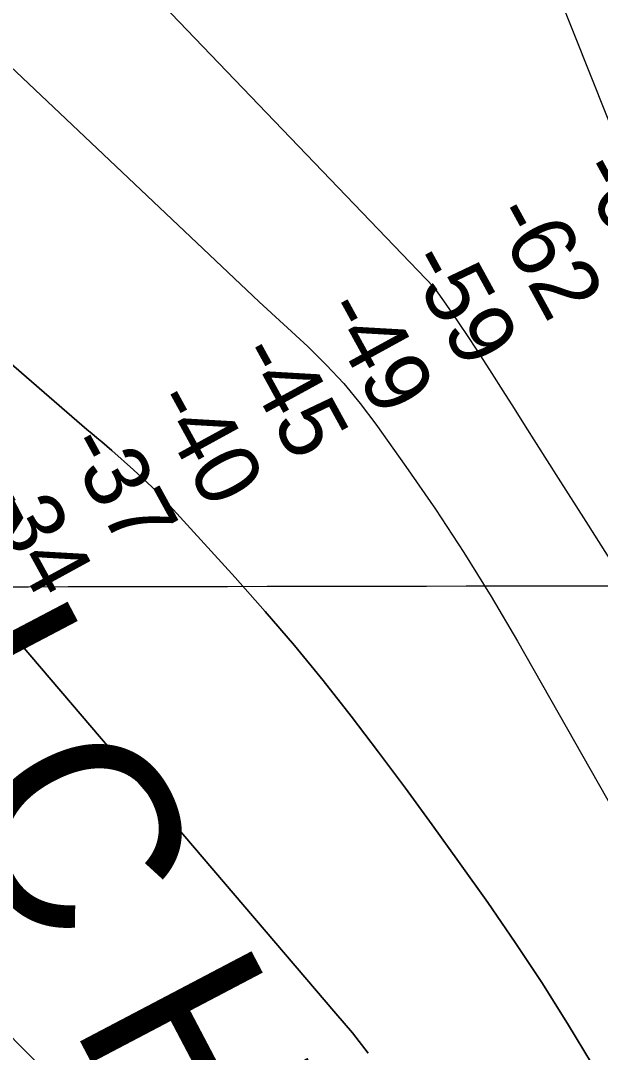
# Model space of a CAD drawing. Extents: x 3329297 to 3367176, y 649250 to 674653.
# Drawn here: x 3340552 to 3341150, y 666285 to 667351 of the extents above; entities that cross this region are included whole.
import ezdxf

# ---------------------------------------------------------------- set-up
doc = ezdxf.new("R2010")
doc.units = 0
for name, color, linetype in [('V-CHAN-NAID', 7, 'Continuous'), ('V-GRID-MAJR', 7, 'Continuous'), ('V-RIVR-EDGE', 7, 'Continuous'), ('V-RIVR-IDEN', 7, 'Continuous'), ('V-RIVR-RANG', 7, 'Continuous'), ('V-TOPO-DPTH', 7, 'Continuous'), ('V-TOPO-MAJR', 7, 'Continuous'), ('V-TOPO-MINR', 7, 'Continuous')]:
    doc.layers.add(name, color=color, linetype=linetype)

msp = doc.modelspace()

# ---------------------------------------------------------------- linework, layer by layer
at = {"layer": 'V-GRID-MAJR'}
msp.add_spline([(3333412.313, 666754.8420000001), (3338670.2060000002, 666762.872), (3343928.099, 666771.667), (3349185.99, 666781.226), (3354443.88, 666791.55), (3359701.768, 666802.639), (3364959.654, 666814.493), (3364959.6550000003, 666814.493)], degree=3, dxfattribs=at)
at = {"layer": 'V-RIVR-EDGE'}
msp.add_spline([(3342816.412489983, 664076.7034879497), (3342812.7598693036, 664100.7302350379), (3342811.243187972, 664114.6948926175), (3342810.4934775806, 664125.1674268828), (3342811.66742752, 664129.4303568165), (3342815.9380288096, 664131.3588117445), (3342822.141879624, 664130.9556684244), (3342827.577800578, 664133.6568478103), (3342827.978067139, 664138.6972967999), (3342825.7126343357, 664163.5222892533), (3342823.0124138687, 664169.3460108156), (3342818.010321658, 664185.2583017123), (3342816.4955581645, 664199.9985605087), (3342816.9054139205, 664208.9170155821), (3342818.0985422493, 664220.9359576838), (3342817.3382837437, 664227.1426852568), (3342814.6639541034, 664243.4370232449), (3342809.2692666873, 664257.4112700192), (3342808.5099671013, 664264.0057982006), (3342808.918863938, 664272.5364526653), (3342814.794367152, 664296.1779059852), (3342814.817381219, 664305.4851205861), (3342810.586095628, 664319.456490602), (3342799.7756245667, 664338.8733707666), (3342790.8840192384, 664350.1416435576), (3342779.6627335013, 664360.2522680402), (3342778.5117976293, 664365.2965527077), (3342779.2969880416, 664369.1726409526), (3342779.6886243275, 664370.7228844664), (3342785.908776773, 664376.9123514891), (3342798.3462049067, 664388.1278837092), (3342804.183351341, 664396.2573126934), (3342807.7080779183, 664410.2095043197), (3342807.3365789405, 664416.8030735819), (3342805.021282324, 664421.4624343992), (3342805.0279947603, 664424.177038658), (3342805.054844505, 664435.0354556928), (3342805.482919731, 664451.3221223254), (3342803.586109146, 664468.3901436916), (3342800.1380961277, 664485.4620007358), (3342800.1543977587, 664492.0546110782), (3342800.5517875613, 664495.9316582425), (3342805.601825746, 664499.409397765), (3342810.274611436, 664507.153902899), (3342811.4543148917, 664513.7436364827), (3342812.6493610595, 664526.5381798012), (3342808.839438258, 664554.0816121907), (3342808.4775284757, 664564.5531875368), (3342811.984994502, 664571.5249682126), (3342819.756349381, 664577.7105995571), (3342825.2124076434, 664588.5555917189), (3342825.6203455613, 664596.6984455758), (3342825.2507644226, 664604.0676160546), (3342821.38905997, 664610.6698155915), (3342817.543657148, 664623.8646254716), (3342808.6443804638, 664632.0304933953), (3342807.4982391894, 664639.0137811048), (3342807.5145408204, 664645.6063914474), (3342805.5889626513, 664651.0403945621), (3342795.54738037, 664667.7407526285), (3342786.278522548, 664683.2757910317), (3342782.785440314, 664682.1210194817), (3342779.3038651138, 664685.6198552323), (3342772.3560574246, 664698.8223364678), (3342765.0051064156, 664705.8209668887), (3342757.6599089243, 664715.1464009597), (3342754.9596884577, 664720.9701225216), (3342754.970236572, 664725.235929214), (3342756.919787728, 664729.496941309), (3342762.3624211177, 664734.912724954), (3342763.164872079, 664745.7692241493), (3342759.3434422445, 664768.6590492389), (3342756.6585644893, 664780.687580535), (3342750.4921115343, 664796.214947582), (3342738.9127516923, 664818.348349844), (3342728.8817175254, 664839.3145146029), (3342718.826710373, 664850.5856641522), (3342704.5269927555, 664870.3989752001), (3342673.2052819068, 664906.9299048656), (3342667.0254040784, 664917.0280633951), (3342662.4005643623, 664928.6735886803), (3342645.7730841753, 664948.1048526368), (3342638.8156872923, 664957.4293277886), (3342632.6415629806, 664969.8542899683), (3342630.7226972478, 664978.0028973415), (3342626.8619517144, 664984.9928974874), (3342614.8689004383, 664996.6566422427), (3342611.3854073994, 664999.3798767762), (3342609.8389995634, 665001.3227154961), (3342609.8514655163, 665006.3641234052), (3342606.758649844, 665010.2498008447), (3342597.8641677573, 665020.3546718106), (3342593.2230264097, 665025.4075867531), (3342592.4666035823, 665033.1655167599), (3342590.9432098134, 665044.415570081), (3342589.416939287, 665054.5022215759), (3342588.2803872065, 665065.3635153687), (3342585.9823511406, 665077.0032871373), (3342585.2307229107, 665086.7002201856), (3342585.254695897, 665096.3952353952), (3342584.878402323, 665101.0498016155), (3342582.947070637, 665104.1570010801), (3342580.2458912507, 665109.5929220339), (3342577.1617058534, 665116.9688049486), (3342577.1760896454, 665122.7858140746), (3342577.1981447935, 665131.7052280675), (3342577.2249945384, 665142.5636451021), (3342577.2537621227, 665154.1976633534), (3342576.123922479, 665167.7735614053), (3342572.696046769, 665192.9892312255), (3342566.9336960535, 665215.1082496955), (3342563.4789705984, 665229.465502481), (3342558.8512541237, 665239.947625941), (3342557.310599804, 665244.2172683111), (3342555.3994054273, 665255.4682805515), (3342553.1052050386, 665268.6592547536), (3342549.2665146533, 665284.5686688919), (3342541.5661198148, 665307.0802825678), (3342537.3367520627, 665321.8272538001), (3342531.9526127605, 665340.067307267), (3342533.512445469, 665343.5536770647), (3342533.5277881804, 665349.7584867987), (3342526.981205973, 665368.3892176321), (3342525.457812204, 665379.6392709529), (3342523.5399053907, 665388.1756789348), (3342518.149053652, 665403.7011281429), (3342515.4651348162, 665416.1174600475), (3342514.3381719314, 665430.8567599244), (3342508.5700676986, 665450.6489747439), (3342503.190722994, 665470.8280312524), (3342492.3812108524, 665490.6327120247), (3342491.626705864, 665499.166243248), (3342490.8741187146, 665508.475375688), (3342486.2809233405, 665532.9183210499), (3342483.597004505, 665545.3346529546), (3342477.8106808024, 665557.7586562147), (3342475.9272950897, 665580.2558860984), (3342474.7984143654, 665594.2195847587), (3342470.1726157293, 665605.4773094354), (3342467.8678672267, 665614.4024769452), (3342467.1296638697, 665629.5286185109), (3342466.3885837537, 665643.491358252), (3342466.8224124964, 665662.1048285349), (3342467.2533644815, 665679.5548969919), (3342463.4146740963, 665695.4643111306), (3342454.928129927, 665713.7120359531), (3342445.6669434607, 665732.3494792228), (3342448.389219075, 665735.4451716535), (3342449.5516619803, 665735.0544942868), (3342454.5777271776, 665728.8372185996), (3342456.1327652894, 665730.3845853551), (3342456.133724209, 665730.7723859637), (3342455.367712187, 665734.6523098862), (3342442.2227661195, 665750.9725387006), (3342428.700567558, 665771.5595331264), (3342413.6482627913, 665800.6819766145), (3342398.602670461, 665832.5190243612), (3342380.4671392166, 665869.4051513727), (3342358.860580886, 665914.0559208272), (3342350.0015788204, 665938.5094143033), (3342337.2655295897, 665963.3602975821), (3342312.2023279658, 666021.5927186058), (3342297.1692015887, 666058.4711742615), (3342281.741562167, 666092.6359845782), (3342274.8100561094, 666112.4310761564), (3342267.5003386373, 666136.1051327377), (3342262.9205681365, 666165.9772866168), (3342261.430736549, 666190.8003612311), (3342261.4499149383, 666198.556373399), (3342257.5699910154, 666197.7903613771), (3342255.2479819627, 666199.7351179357), (3342252.934603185, 666205.1700799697), (3342252.565022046, 666212.5392504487), (3342252.5813236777, 666219.1318607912), (3342250.2880822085, 666232.7106356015), (3342241.8197575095, 666258.3265719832), (3342236.0708316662, 666285.8747989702), (3342231.8126963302, 666288.9877519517), (3342227.553602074, 666291.7129043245), (3342219.0488384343, 666302.5924175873), (3342218.6715859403, 666306.8591831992), (3342219.0728114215, 666312.2874327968), (3342210.1581920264, 666314.2484909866), (3342205.12829115, 666318.9145642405), (3342203.978314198, 666324.3466495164), (3342203.99269799, 666330.1636586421), (3342202.075750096, 666339.0878672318), (3342191.6482850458, 666356.5647854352), (3342180.044952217, 666369.0031724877), (3342175.412441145, 666377.5462929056), (3342164.9897706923, 666396.9622141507), (3342154.5805251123, 666421.8073439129), (3342139.946706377, 666463.3384479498), (3342130.699903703, 666487.7929003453), (3342122.98991967, 666506.4265079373), (3342111.795483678, 666527.3955494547), (3342098.676428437, 666554.1863946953), (3342094.827189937, 666565.8300021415), (3342092.5397019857, 666581.7355806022), (3342088.6933402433, 666594.5425898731), (3342085.2482039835, 666612.7778487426), (3342082.168813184, 666622.0927346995), (3342072.8855715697, 666631.8107639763), (3342063.224118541, 666645.4077582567), (3342057.437794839, 666657.8317615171), (3342049.7316464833, 666678.0165715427), (3342048.217841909, 666693.1446309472), (3342050.165475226, 666696.6300418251), (3342050.960254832, 666704.3841361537), (3342046.7059551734, 666709.0482915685), (3342039.356922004, 666716.8225232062), (3342032.407196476, 666729.2494032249), (3342015.8104017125, 666761.0902866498), (3342003.061886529, 666780.8997620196), (3341996.0949004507, 666786.3462310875), (3341994.9468413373, 666792.5539175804), (3341992.629626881, 666796.4376771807), (3341982.9729684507, 666811.9736745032), (3341967.1306786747, 666835.2810267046), (3341953.5912195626, 666848.8876101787), (3341946.6319048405, 666857.4364841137), (3341940.452985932, 666867.9224432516), (3341935.814721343, 666874.1387600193), (3341919.1642270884, 666884.2628093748), (3341915.6884054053, 666890.0884487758), (3341911.4475306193, 666900.1818127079), (3341899.847074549, 666913.7836015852), (3341894.8238861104, 666921.1642790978), (3341889.03276781, 666931.6492793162), (3341869.317266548, 666956.9052237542), (3341855.0127543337, 666974.7795317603), (3341848.8175337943, 666978.6728805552), (3341839.5304565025, 666986.8397073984), (3341829.093402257, 667000.4386195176), (3341821.7616296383, 667015.1932621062), (3341819.0709983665, 667024.8949897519), (3341817.1473380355, 667031.1045940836), (3341806.3080993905, 667038.8874559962), (3341788.125581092, 667056.7713531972), (3341778.463169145, 667069.9805468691), (3341769.5590978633, 667076.207411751), (3341762.975117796, 667079.7139188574), (3341756.0177209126, 667089.0383940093), (3341748.28759957, 667099.5281888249), (3341738.624228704, 667112.3495818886), (3341730.887394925, 667120.1247724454), (3341719.2869388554, 667133.7265613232), (3341714.656345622, 667143.0452829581), (3341706.5460950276, 667156.6384415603), (3341694.949474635, 667171.7914328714), (3341682.2191789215, 667198.9691198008), (3341673.732634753, 667217.2168446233), (3341665.656905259, 667244.7708251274), (3341658.3529413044, 667270.7716853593), (3341654.4998671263, 667280.8640903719), (3341646.7850884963, 667297.5586949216), (3341633.668910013, 667325.5129419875), (3341621.3129900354, 667347.2604614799), (3341603.9194978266, 667370.5716493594), (3341601.613790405, 667379.1090162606), (3341595.053783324, 667392.3105385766), (3341586.5720337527, 667412.4972664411), (3341578.097955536, 667435.7863991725), (3341568.43362575, 667448.219991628), (3341554.132949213, 667467.6455020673), (3341537.518893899, 667492.5059745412), (3341516.655333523, 667523.9696054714), (3341476.0791486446, 667581.8525826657), (3341429.711845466, 667650.2205600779), (3341398.0282248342, 667697.2230650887), (3341370.980950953, 667737.2336521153), (3341354.758531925, 667763.644368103), (3341343.5487532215, 667778.4085998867), (3341338.9047351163, 667782.298113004), (3341332.3313031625, 667790.0704268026), (3341325.39020791, 667805.9875122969), (3341317.6543330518, 667814.1505034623), (3341305.2773168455, 667827.3664095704), (3341300.6380933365, 667833.19492573), (3341282.889403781, 667869.6922932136), (3341259.7239716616, 667911.244493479), (3341224.57795422, 667969.5018464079), (3341190.5723245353, 668018.4491079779), (3341159.668140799, 668067.0008975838), (3341126.024420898, 668105.476583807), (3341085.807269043, 668151.7245838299), (3341034.769098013, 668213.1236573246), (3340998.796656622, 668250.8294958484), (3340967.0746792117, 668282.3199765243), (3340929.9206165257, 668312.6604802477), (3340887.354605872, 668349.9948197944), (3340852.52159332, 668378.0027663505), (3340818.0763813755, 668406.0097539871), (3340783.6436353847, 668439.0581495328), (3340747.6692761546, 668475.9883868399), (3340722.9200383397, 668504.3592020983), (3340704.3583497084, 668525.734263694), (3340693.9155419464, 668537.0063721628), (3340680.745663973, 668543.2437851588), (3340672.610481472, 668546.7541279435), (3340664.4810524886, 668552.5912743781), (3340650.9348809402, 668563.4832535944), (3340645.9068979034, 668568.9249280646), (3340640.884668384, 668576.6934061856), (3340634.69807812, 668584.0769604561), (3340619.617005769, 668601.5653856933), (3340609.5418613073, 668604.6927224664), (3340603.7354002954, 668608.9729129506), (3340599.0952178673, 668614.4136285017), (3340595.621314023, 668621.0148691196), (3340589.431847, 668627.2350215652), (3340567.761041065, 668645.9031502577), (3340549.9548163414, 668659.1324812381), (3340496.933531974, 668702.6975213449), (3340430.762506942, 668760.6437872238), (3340383.932607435, 668798.7642761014), (3340346.7670377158, 668824.451172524), (3340316.957213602, 668845.0784415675), (3340289.8562402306, 668863.3721945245), (3340255.4119872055, 668891.7669827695), (3340209.373031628, 668936.0903635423), (3340181.1297526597, 668962.9186066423), (3340159.060598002, 668977.3218875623), (3340134.28834612, 668996.3854882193), (3340120.7469691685, 669009.2164704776), (3340113.399853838, 669017.7663033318), (3340109.9240321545, 669023.591942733), (3340107.6029820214, 669025.9244998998), (3340099.8488876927, 669026.7192795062), (3340094.4225559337, 669027.896106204), (3340089.386901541, 669030.2353758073), (3340085.13643756, 669036.4507336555), (3340084.7649385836, 669043.0443029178), (3340082.0580056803, 669046.1534202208), (3340066.189825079, 669058.990155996), (3340051.0962867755, 669071.4371733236), (3340041.8044148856, 669077.6649971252), (3339987.6072627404, 669116.1915060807), (3339929.5186796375, 669149.2983957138), (3339882.276047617, 669177.337027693), (3339823.8034995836, 669211.9960786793), (3339768.8192391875, 669245.8708981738), (3339704.9395377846, 669289.4627880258), (3339659.643580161, 669320.5990302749), (3339613.9790003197, 669359.4922436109), (3339576.0320758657, 669382.8542542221), (3339562.8717870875, 669392.9696733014), (3339559.38541729, 669394.5295060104), (3339555.894252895, 669394.1503356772), (3339553.169100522, 669389.8912414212), (3339550.8394201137, 669388.7335931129), (3339546.194443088, 669392.2353056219), (3339540.385105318, 669395.3520942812), (3339537.276946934, 669393.0329619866), (3339533.010181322, 669392.6557094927), (3339518.6749836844, 669398.12039803), (3339507.8328682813, 669404.7398581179), (3339498.9297559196, 669411.3545236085), (3339490.0103419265, 669411.3765787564), (3339486.5316434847, 669416.0388163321), (3339483.4330742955, 669417.5976901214), (3339473.3579298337, 669420.7250268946), (3339460.5777703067, 669427.7370821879), (3339447.7995286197, 669435.5247386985), (3339435.4090875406, 669443.3114362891), (3339423.800001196, 669453.423019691), (3339413.3571934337, 669464.6951281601), (3339407.9442865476, 669471.3011633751), (3339393.6158013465, 669479.4804561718), (3339378.1277499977, 669489.2138281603), (3339357.606921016, 669502.4498715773), (3339355.6736714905, 669504.7814698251), (3339358.392111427, 669506.3259598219), (3339359.5631846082, 669509.4254879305), (3339359.1792196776, 669510.977649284), (3339356.4751635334, 669515.2501684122), (3339347.17178461, 669516.8243849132), (3339341.3442273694, 669512.5729620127), (3339338.2437403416, 669513.3562345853), (3339320.8233983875, 669525.80900543), (3339311.1504383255, 669534.7523924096), (3339296.0607356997, 669548.7506121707), (3339293.349967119, 669550.3085270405), (3339286.3666794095, 669549.1623857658), (3339280.930758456, 669546.4612063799), (3339277.0527523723, 669546.4707955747), (3339268.141968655, 669549.9830561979), (3339250.7149142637, 669559.7212227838), (3339229.037395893, 669575.6747472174), (3339210.8385759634, 669586.9660340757), (3339202.3270998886, 669595.1309430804), (3339200.3986449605, 669599.4015443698), (3339200.024269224, 669604.8317118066), (3339198.1006088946, 669611.041316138), (3339183.005152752, 669622.712732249), (3339166.3536995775, 669632.4489809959)], degree=3, dxfattribs=at)
at = {"layer": 'V-TOPO-DPTH'}
for points in [[(3340515.784035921, 667018.4560572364), (3340604.4872390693, 666941.6365802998), (3340609.6230204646, 666937.2259392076), (3340614.7828812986, 666932.8438908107), (3340619.978861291, 666928.5047314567), (3340625.1989207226, 666924.1941647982), (3340630.4093139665, 666919.8725976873), (3340635.5827492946, 666915.5077819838), (3340640.7007477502, 666911.0780933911), (3340645.781788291, 666906.6051562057), (3340668.025848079, 666886.7730010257), (3340677.791540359, 666877.787262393), (3340687.3621001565, 666868.6044345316), (3340696.6399612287, 666859.125972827), (3340705.7226898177, 666849.4504218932), (3340773.1181377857, 666775.3602691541), (3340804.0907243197, 666740.4610839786), (3340834.4790536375, 666705.0725049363), (3340863.9909971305, 666668.949835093), (3340892.9186834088, 666632.3377713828), (3340921.1740805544, 666595.1858627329), (3340949.1182735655, 666557.8043177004), (3340976.595660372, 666520.0783180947), (3341003.761843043, 666482.1226821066), (3341033.830538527, 666439.5552035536), (3341062.1098839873, 666398.4595442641), (3341089.704056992, 666356.9207476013), (3341116.270471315, 666314.7172448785), (3341142.1517131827, 666272.0706047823)], [(3341142.1517131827, 666272.0706047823), (3341116.270471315, 666314.7172448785), (3341089.704056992, 666356.9207476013), (3341062.1098839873, 666398.4595442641), (3341033.830538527, 666439.5552035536), (3341003.761843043, 666482.1226821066), (3340976.595660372, 666520.0783180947), (3340949.1182735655, 666557.8043177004), (3340921.1740805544, 666595.1858627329), (3340892.9186834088, 666632.3377713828), (3340863.9909971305, 666668.949835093), (3340834.4790536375, 666705.0725049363), (3340804.0907243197, 666740.4610839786), (3340773.1181377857, 666775.3602691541), (3340705.7226898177, 666849.4504218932), (3340696.6399612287, 666859.125972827), (3340687.3621001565, 666868.6044345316), (3340677.791540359, 666877.787262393), (3340668.025848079, 666886.7730010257), (3340645.781788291, 666906.6051562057), (3340640.7007477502, 666911.0780933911), (3340635.5827492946, 666915.5077819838), (3340630.4093139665, 666919.8725976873), (3340625.1989207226, 666924.1941647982), (3340619.978861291, 666928.5047314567), (3340614.7828812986, 666932.8438908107), (3340609.6230204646, 666937.2259392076), (3340604.4872390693, 666941.6365802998), (3340515.784035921, 667018.4560572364)], [(3340771.2787898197, 666067.7999383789), (3340232.13029941, 666615.6760300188), (3340229.425696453, 666619.2219769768), (3340226.7191783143, 666622.7664623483), (3340222.617289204, 666628.1353334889), (3340219.2620926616, 666632.4489916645), (3340215.85793739, 666636.7229578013), (3340212.3803440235, 666640.9373858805), (3340208.853791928, 666645.112121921), (3340205.243418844, 666649.2132764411), (3340201.5703573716, 666653.2561164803), (3340197.803263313, 666657.2114847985), (3340193.9734808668, 666661.1085386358), (3340064.648950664, 666789.6459200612), (3340032.6700920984, 666821.2123163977), (3340000.5477135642, 666852.6309653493), (3339968.2100550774, 666883.8279932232), (3339935.7288766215, 666914.8772737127)], [(3340771.2787898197, 666067.7999383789), (3340232.13029941, 666615.6760300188), (3340229.425696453, 666619.2219769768), (3340226.7191783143, 666622.7664623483), (3340222.617289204, 666628.1353334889), (3340219.2620926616, 666632.4489916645), (3340215.85793739, 666636.7229578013), (3340212.3803440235, 666640.9373858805), (3340208.853791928, 666645.112121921), (3340205.243418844, 666649.2132764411), (3340201.5703573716, 666653.2561164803), (3340197.803263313, 666657.2114847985), (3340193.9734808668, 666661.1085386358), (3340064.648950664, 666789.6459200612), (3340032.6700920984, 666821.2123163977), (3340000.5477135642, 666852.6309653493), (3339968.2100550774, 666883.8279932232), (3339935.7288766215, 666914.8772737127)], [(3340508.91711353, 666756.4910139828), (3340876.943181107, 666324.9032894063), (3340894.2299979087, 666305.0608610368), (3340910.302791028, 666284.2228832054)], [(3340910.302791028, 666284.2228832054), (3340894.2299979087, 666305.0608610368), (3340876.943181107, 666324.9032894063), (3340508.91711353, 666756.4910139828)]]:
    msp.add_lwpolyline(points, dxfattribs=at)
at = {"layer": 'V-TOPO-MAJR'}
msp.add_lwpolyline([(3340406.3447181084, 667443.6637368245), (3340508.0460336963, 667334.2910983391), (3340797.918971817, 667060.3825286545), (3340848.01030639, 667014.0276851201), (3340867.0903643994, 666995.2371903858), (3340885.339846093, 666975.7171379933), (3340902.343463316, 666955.1027491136), (3340918.516504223, 666933.7588025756), (3340949.4640005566, 666890.1662050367), (3340979.8010785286, 666846.0399841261), (3341009.23178672, 666801.3364269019), (3341037.3029402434, 666755.7668652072), (3341064.4677239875, 666709.6199671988), (3341291.5625543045, 666310.19277351)], dxfattribs=at)
at = {"layer": 'V-TOPO-MINR'}
for points in [[(3339822.8375603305, 668309.1723428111), (3340137.134240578, 667960.7086974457), (3340184.451966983, 667908.5566591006), (3340231.97314176, 667856.5917744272), (3340279.799489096, 667804.9076202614), (3340327.829284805, 667753.4106197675), (3340378.9447437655, 667698.9277023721), (3340402.31641122, 667675.6972424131), (3340978.0768605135, 667075.4802250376), (3340990.534827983, 667057.9611672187), (3341002.7834024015, 667040.299616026), (3341014.7178872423, 667022.4243247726), (3341026.4429790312, 667004.4065401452), (3341037.999782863, 666986.2747368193), (3341049.5417473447, 666968.1335050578), (3341061.0614528, 666949.9781306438), (3341072.5663189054, 666931.8133277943), (3341106.5114003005, 666878.1453368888), (3341135.027142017, 666833.1710084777), (3341163.6088356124, 666788.2387345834)], [(3341173.8361770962, 667209.866692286), (3341056.328276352, 667505.072451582), (3341058.080097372, 667517.9068678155), (3341062.905037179, 667526.1118435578), (3341072.339655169, 667527.3726585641), (3341084.847391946, 667524.0040330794), (3341114.657445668, 667494.9964143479), (3341144.688970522, 667466.2226516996), (3341175.052702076, 667437.7996731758)], [(3340515.784035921, 667018.4560572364), (3340604.4872390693, 666941.6365802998), (3340609.6230204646, 666937.2259392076), (3340614.7828812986, 666932.8438908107), (3340619.978861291, 666928.5047314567), (3340625.1989207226, 666924.1941647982), (3340630.4093139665, 666919.8725976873), (3340635.5827492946, 666915.5077819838), (3340640.7007477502, 666911.0780933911), (3340645.781788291, 666906.6051562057), (3340668.025848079, 666886.7730010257), (3340677.791540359, 666877.787262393), (3340687.3621001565, 666868.6044345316), (3340696.6399612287, 666859.125972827), (3340705.7226898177, 666849.4504218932), (3340773.1181377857, 666775.3602691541), (3340804.0907243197, 666740.4610839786), (3340834.4790536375, 666705.0725049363), (3340863.9909971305, 666668.949835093), (3340892.9186834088, 666632.3377713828), (3340921.1740805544, 666595.1858627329), (3340949.1182735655, 666557.8043177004), (3340976.595660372, 666520.0783180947), (3341003.761843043, 666482.1226821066), (3341033.830538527, 666439.5552035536), (3341062.1098839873, 666398.4595442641), (3341089.704056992, 666356.9207476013), (3341116.270471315, 666314.7172448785), (3341142.1517131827, 666272.0706047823)], [(3339935.7288766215, 666914.8772737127), (3339968.2100550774, 666883.8279932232), (3340000.5477135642, 666852.6309653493), (3340032.6700920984, 666821.2123163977), (3340064.648950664, 666789.6459200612), (3340193.9734808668, 666661.1085386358), (3340197.803263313, 666657.2114847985), (3340201.5703573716, 666653.2561164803), (3340205.243418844, 666649.2132764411), (3340208.853791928, 666645.112121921), (3340212.3803440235, 666640.9373858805), (3340215.85793739, 666636.7229578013), (3340219.2620926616, 666632.4489916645), (3340222.617289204, 666628.1353334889), (3340226.7191783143, 666622.7664623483), (3340229.425696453, 666619.2219769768), (3340232.13029941, 666615.6760300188), (3340771.2787898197, 666067.7999383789)], [(3340508.91711353, 666756.4910139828), (3340876.943181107, 666324.9032894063), (3340894.2299979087, 666305.0608610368), (3340910.302791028, 666284.2228832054)]]:
    msp.add_lwpolyline(points, dxfattribs=at)

# ---------------------------------------------------------------- texts
at = {"layer": 'V-CHAN-NAID'}
msp.add_text('LONGWOOD PLANTATION "216B" (216.2)', height=100.00000200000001, rotation=31.835282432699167, dxfattribs=at).set_placement((3338819.2077042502, 666779.6249427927))
at = {"layer": 'V-RIVR-IDEN'}
msp.add_text('M A N C H A C', height=199.99959799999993, rotation=297.7390730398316, dxfattribs=at).set_placement((3340097.9170523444, 667275.7189433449))
at = {"layer": 'V-RIVR-RANG'}
for s, p in [('-67', (3341124.4022425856, 667196.0237217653)), ('-62', (3341035.4453822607, 667150.269460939)), ('-59', (3340948.00256047, 667101.7504283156)), ('-49', (3340861.1943690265, 667052.0746746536)), ('-45', (3340772.485286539, 667005.8680841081)), ('-40', (3340685.043464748, 666957.3490514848)), ('-37', (3340595.695077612, 666912.3095406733)), ('-34', (3340508.132204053, 666864.0114935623))]:
    msp.add_text(s, height=67, rotation=298.7131111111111, dxfattribs=at).set_placement(p)

doc.saveas('drawing.dxf')
